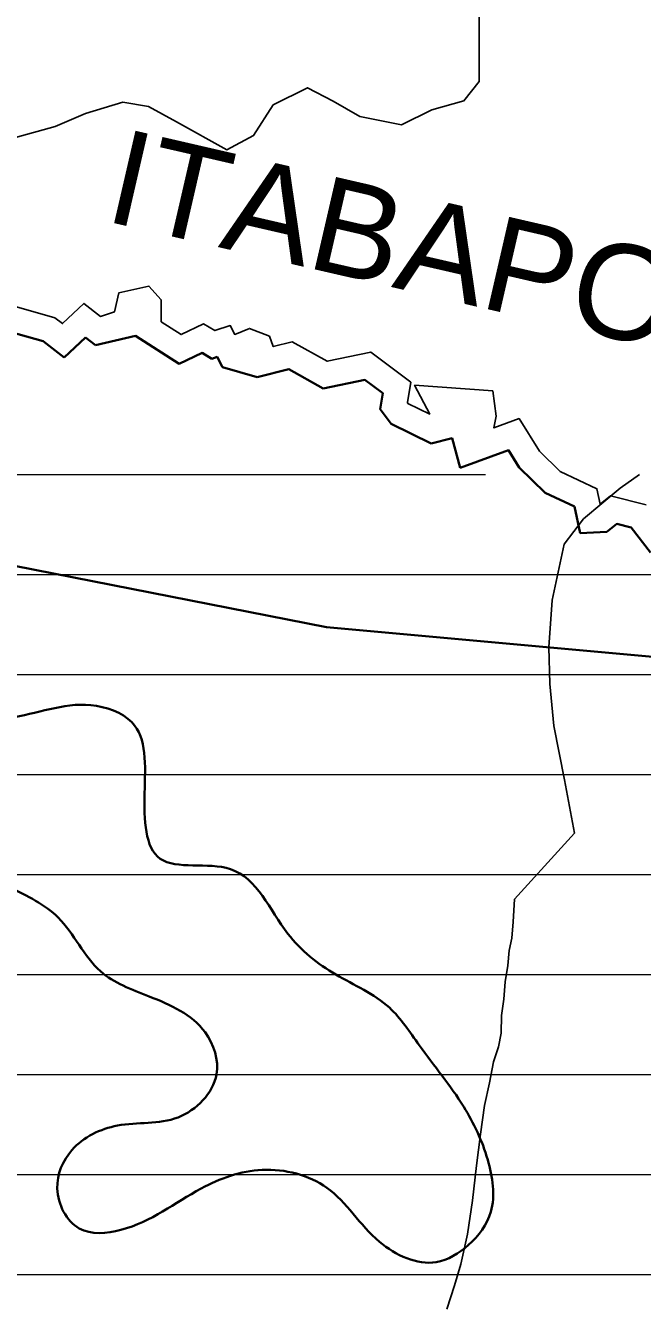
# Model space of a CAD drawing. Extents: x -10.5 to 30.8, y 18.4 to 58.7.
# Drawn here: x 10.83 to 12.063, y 50.987 to 53.552 of the extents above; entities that cross this region are included whole.
import ezdxf

# ---------------------------------------------------------------- set-up
doc = ezdxf.new("R2010")
doc.units = 0
doc.header["$LTSCALE"] = 0.08
doc.linetypes.add('DASH_DOUBLE_DOT', pattern=[9.2, 5, -1.2, 0.3, -1.2, 0.3, -1.2])
for name, color, linetype, lineweight in [('12', 7, 'Continuous', 25), ('20', 7, 'DASH_DOUBLE_DOT', 35), ('29', 7, 'Continuous', 13), ('43', 7, 'Continuous', 13), ('47', 7, 'Continuous', 25), ('48', 7, 'Continuous', 35), ('9', 7, 'Continuous', 25)]:
    doc.layers.add(name, color=color, linetype=linetype, lineweight=lineweight)

msp = doc.modelspace()

# ---------------------------------------------------------------- linework, layer by layer
at = {"layer": '12'}
msp.add_lwpolyline([(10.81009, 53.32855), (10.88946, 53.35065), (10.94956, 53.37692), (11.02464, 53.39903), (11.07605, 53.39064), (11.13166, 53.35978), (11.2322, 53.30424), (11.28587, 53.33257), (11.32466, 53.39363), (11.39336, 53.42802), (11.4447, 53.40126), (11.49817, 53.37041), (11.58169, 53.35371), (11.64181, 53.38406), (11.70616, 53.40214), (11.7363, 53.44079), (11.73648, 53.49181), (11.73684, 53.59589)], dxfattribs=at)
at = {"layer": '20'}
msp.add_lwpolyline([(10.79886, 52.94002), (10.86532, 52.92121), (10.90749, 52.88884), (10.94985, 52.92896), (10.96981, 52.91336), (11.0497, 52.93231), (11.13687, 52.8758), (11.183, 52.8977), (11.20219, 52.88615), (11.21328, 52.88976), (11.22374, 52.86923), (11.29305, 52.84918), (11.35593, 52.86524), (11.42457, 52.82671), (11.50783, 52.84434), (11.54416, 52.81703), (11.53858, 52.78532), (11.56057, 52.7561), (11.64038, 52.71687), (11.6825, 52.72762), (11.69896, 52.66809), (11.79498, 52.70359), (11.81682, 52.66889), (11.86855, 52.618), (11.92715, 52.59057), (11.93861, 52.53739), (11.99156, 52.54006), (12.0115, 52.55589), (12.0406, 52.54866), (12.07895, 52.49862)], dxfattribs=at)
at = {"layer": '29', "linetype": 'DASH_DOUBLE_DOT', "lineweight": 35}
msp.add_lwpolyline([(10.79886, 52.94002), (10.86532, 52.92121), (10.90749, 52.88884), (10.94985, 52.92896), (10.96981, 52.91336), (11.0497, 52.93231), (11.13687, 52.8758), (11.183, 52.8977), (11.20219, 52.88615), (11.21328, 52.88976), (11.22374, 52.86923), (11.29305, 52.84918), (11.35593, 52.86524), (11.42457, 52.82671), (11.50783, 52.84434), (11.54416, 52.81703), (11.53858, 52.78532), (11.56057, 52.7561), (11.64038, 52.71687), (11.6825, 52.72762), (11.69896, 52.66809), (11.79498, 52.70359), (11.81682, 52.66889), (11.86855, 52.618), (11.92715, 52.59057), (11.93861, 52.53739), (11.99156, 52.54006), (12.0115, 52.55589), (12.0406, 52.54866), (12.07895, 52.49862)], dxfattribs=at)
at = {"layer": '43'}
for p, q in [((4.719, 52.6548), (11.74932, 52.6548)), ((4.719, 52.4548), (12.30135, 52.4548)), ((4.719, 52.2548), (12.92186, 52.2548)), ((4.719, 52.0548), (14.29713, 52.0548)), ((4.719, 51.8548), (15.2159, 51.8548)), ((4.719, 51.6548), (15.4387, 51.6548)), ((4.719, 51.4548), (15.65105, 51.4548)), ((4.719, 51.2548), (15.6669, 51.2548)), ((4.719, 51.0548), (15.6026, 51.0548))]:
    msp.add_line(p, q, dxfattribs=at)
msp.add_lwpolyline([(12.07895, 52.49862), (12.0406, 52.54866), (12.0115, 52.55589), (11.99156, 52.54006), (11.93861, 52.53739), (11.92715, 52.59057), (11.86855, 52.618), (11.81682, 52.66889), (11.79498, 52.70359), (11.69896, 52.66809), (11.6825, 52.72762), (11.64038, 52.71687), (11.56057, 52.7561), (11.53858, 52.78532), (11.54416, 52.81703), (11.50783, 52.84434), (11.42457, 52.82671), (11.35593, 52.86524), (11.29305, 52.84918), (11.22374, 52.86923), (11.21328, 52.88976), (11.20219, 52.88615), (11.183, 52.8977), (11.13687, 52.8758), (11.0497, 52.93231), (10.96981, 52.91336), (10.94985, 52.92896), (10.90749, 52.88884), (10.86532, 52.92121), (10.79886, 52.94002)], dxfattribs=at)
msp.add_lwpolyline([(12.07895, 52.49862), (12.0406, 52.54866), (12.0115, 52.55589), (11.99156, 52.54006), (11.93861, 52.53739), (11.92715, 52.59057), (11.86855, 52.618), (11.81682, 52.66889), (11.79498, 52.70359), (11.69896, 52.66809), (11.6825, 52.72762), (11.64038, 52.71687), (11.56057, 52.7561), (11.53858, 52.78532), (11.54416, 52.81703), (11.50783, 52.84434), (11.42457, 52.82671), (11.35593, 52.86524), (11.29305, 52.84918), (11.22374, 52.86923), (11.21328, 52.88976), (11.20219, 52.88615), (11.183, 52.8977), (11.13687, 52.8758), (11.0497, 52.93231), (10.96981, 52.91336), (10.94985, 52.92896), (10.90749, 52.88884), (10.86532, 52.92121), (10.79886, 52.94002)], dxfattribs=at)
at = {"layer": '47'}
msp.add_lwpolyline([(10.80273, 52.99244), (10.88884, 52.96807), (10.90399, 52.95645), (10.94663, 52.99684), (10.97985, 52.97087), (11.00779, 52.98006), (11.01613, 53.01787), (11.07656, 53.03135), (11.1012, 53.00392), (11.1012, 52.96029), (11.14076, 52.93465), (11.18587, 52.95608), (11.20861, 52.94239), (11.2392, 52.95234), (11.24811, 52.93484), (11.27746, 52.94684), (11.31756, 52.93115), (11.32521, 52.91054), (11.36316, 52.92023), (11.43287, 52.8811), (11.52006, 52.89957), (11.60035, 52.83921), (11.59317, 52.79842), (11.59432, 52.79689), (11.6379, 52.77547), (11.60756, 52.83308), (11.7639, 52.82173), (11.77068, 52.77153), (11.76625, 52.74787), (11.81631, 52.76638), (11.85721, 52.70139), (11.89837, 52.6609), (11.97211, 52.62638), (11.97874, 52.59563), (11.99933, 52.61197), (12.07051, 52.59429)], dxfattribs=at)
at = {"layer": '48'}
msp.add_lwpolyline([(13.1676, 52.19155), (11.43157, 52.34934), (10.2618, 52.57907), (10.23722, 52.58384)], dxfattribs=at)
for points in [[(9.65288, 51.32868), (9.76997, 51.37657), (9.84527, 51.42597), (9.95322, 51.50546), (10.08447, 51.64143), (10.20418, 51.75175), (10.30232, 51.72218), (10.43551, 51.77992), (10.48123, 51.87206), (10.59199, 51.89414), (10.66489, 51.88631), (10.79849, 51.82941), (10.89531, 51.76862), (10.97971, 51.66139), (11.07697, 51.61101), (11.18902, 51.53925), (11.21163, 51.45508), (11.1348, 51.36926), (11.0138, 51.35276), (10.92283, 51.30393), (10.89344, 51.22683), (10.93716, 51.14711), (11.02072, 51.14411), (11.18111, 51.22692), (11.30298, 51.26423), (11.43223, 51.22833), (11.53753, 51.12035), (11.65089, 51.07981), (11.7151, 51.11397), (11.75972, 51.1801), (11.75365, 51.28452), (11.7058, 51.39045), (11.61683, 51.51347), (11.55723, 51.58856), (11.45018, 51.65492), (11.35423, 51.73652), (11.23937, 51.86569), (11.09902, 51.88636), (11.06793, 52.01773), (11.0425, 52.15932), (10.96026, 52.19353), (10.79705, 52.16813), (10.65691, 52.194), (10.57097, 52.26482), (10.44651, 52.29012), (10.28177, 52.22831), (10.17294, 52.12801), (10.09523, 52.02138), (10.02265, 51.93555)], [(10.02265, 51.93555), (10.09523, 52.02138), (10.17294, 52.12801), (10.28177, 52.22831), (10.44651, 52.29012), (10.57097, 52.26482), (10.65691, 52.194), (10.79705, 52.16813), (10.96026, 52.19353), (11.0425, 52.15932), (11.06793, 52.01773), (11.09902, 51.88636), (11.23937, 51.86569), (11.35423, 51.73652), (11.45018, 51.65492), (11.55723, 51.58856), (11.61683, 51.51347), (11.7058, 51.39045), (11.75365, 51.28452), (11.75972, 51.1801), (11.7151, 51.11397), (11.65089, 51.07981), (11.53753, 51.12035), (11.43223, 51.22833), (11.30298, 51.26423), (11.18111, 51.22692), (11.02072, 51.14411), (10.93716, 51.14711), (10.89344, 51.22683), (10.92283, 51.30393), (11.0138, 51.35276), (11.1348, 51.36926), (11.21163, 51.45508), (11.18902, 51.53925), (11.07697, 51.61101), (10.97971, 51.66139), (10.89531, 51.76862), (10.79849, 51.82941), (10.66489, 51.88631), (10.59199, 51.89414), (10.48123, 51.87206), (10.43551, 51.77992), (10.30232, 51.72218), (10.20418, 51.75175), (10.08447, 51.64143), (9.95322, 51.50546), (9.84527, 51.42597), (9.76997, 51.37657), (9.65288, 51.32868)], [(9.65288, 51.32868), (9.76997, 51.37657), (9.84527, 51.42597), (9.95322, 51.50546), (10.08447, 51.64143), (10.20418, 51.75175), (10.30232, 51.72218), (10.43551, 51.77992), (10.48123, 51.87206), (10.59199, 51.89414), (10.66489, 51.88631), (10.79849, 51.82941), (10.89531, 51.76862), (10.97971, 51.66139), (11.07697, 51.61101), (11.18902, 51.53925), (11.21163, 51.45508), (11.1348, 51.36926), (11.0138, 51.35276), (10.92283, 51.30393), (10.89344, 51.22683), (10.93716, 51.14711), (11.02072, 51.14411), (11.18111, 51.22692), (11.30298, 51.26423), (11.43223, 51.22833), (11.53753, 51.12035), (11.65089, 51.07981), (11.7151, 51.11397), (11.75972, 51.1801), (11.75365, 51.28452), (11.7058, 51.39045), (11.61683, 51.51347), (11.55723, 51.58856), (11.45018, 51.65492), (11.35423, 51.73652), (11.23937, 51.86569), (11.09902, 51.88636), (11.06793, 52.01773), (11.0425, 52.15932), (10.96026, 52.19353), (10.79705, 52.16813), (10.65691, 52.194), (10.57097, 52.26482), (10.44651, 52.29012), (10.28177, 52.22831), (10.17294, 52.12801), (10.09523, 52.02138), (10.02265, 51.93555)], [(10.67227, 49.07775), (10.72643, 48.99765), (10.78516, 48.90176), (10.8317, 48.76462), (10.9024, 48.70477), (10.96051, 48.71832), (11.01339, 48.73205), (11.06999, 48.83422), (11.11703, 48.95758), (11.17669, 49.13258), (11.26616, 49.27005), (11.3419, 49.32985), (11.45486, 49.40395), (11.55975, 49.4106), (11.63721, 49.38698), (11.73969, 49.33641), (11.74013, 49.34682), (11.83961, 49.4735), (11.89862, 49.6329), (11.98612, 49.72354), (12.07709, 49.77238), (12.1746, 49.85224), (12.17678, 49.90426), (12.22275, 50.12665), (12.25215, 50.20375), (12.2837, 50.20783), (12.38424, 50.23548), (12.52112, 50.25662), (12.64168, 50.26271), (12.78838, 50.39291), (12.90894, 50.399), (13.04779, 50.46696), (13.13269, 50.62022), (13.21171, 50.75806), (13.39234, 50.82451), (13.44025, 50.96868), (13.46858, 51.14481), (13.53932, 51.21), (13.68142, 51.23095), (13.76586, 51.24876), (13.77111, 51.37362), (13.71785, 51.59957), (13.62907, 51.60276), (13.50742, 51.57065), (13.38074, 51.41889), (13.30696, 51.40591), (13.25367, 51.50682), (13.23935, 51.66364)], [(13.23935, 51.66364), (13.25367, 51.50682), (13.30696, 51.40591), (13.38074, 51.41889), (13.50742, 51.57065), (13.62907, 51.60276), (13.71785, 51.59957), (13.77111, 51.37362), (13.76586, 51.24876), (13.68142, 51.23095), (13.53932, 51.21), (13.46858, 51.14481), (13.44025, 50.96868), (13.39234, 50.82451), (13.21171, 50.75806), (13.13269, 50.62022), (13.04779, 50.46696), (12.90894, 50.399), (12.78838, 50.39291), (12.64168, 50.26271), (12.52112, 50.25662), (12.38424, 50.23548), (12.2837, 50.20783), (12.25215, 50.20375), (12.22275, 50.12665), (12.17678, 49.90426), (12.1746, 49.85224), (12.07709, 49.77238), (11.98612, 49.72354), (11.89862, 49.6329), (11.83961, 49.4735), (11.74013, 49.34682), (11.73969, 49.33641), (11.71814, 49.33856)]]:
    msp.add_spline(points, degree=3, dxfattribs=at)
at = {"layer": '9'}
for points in [[(12.05738, 52.6548), (12.0185, 52.62727), (11.94542, 52.56636), (11.90667, 52.51551), (11.88271, 52.40337), (11.87595, 52.30952), (11.87784, 52.23604), (11.88612, 52.15233), (11.90717, 52.04407), (11.92715, 51.9374)], [(11.92715, 51.9374), (11.80747, 51.80521), (11.80469, 51.76022), (11.80198, 51.72773), (11.7968, 51.70276), (11.79411, 51.67277), (11.78889, 51.64029), (11.78617, 51.6053), (11.78094, 51.57283), (11.78073, 51.53782), (11.77554, 51.51035), (11.76532, 51.4804), (11.75754, 51.43793), (11.74723, 51.39298), (11.73935, 51.33552), (11.73144, 51.27305), (11.72347, 51.20309), (11.71302, 51.13564), (11.70011, 51.07569), (11.68732, 51.03326), (11.67198, 50.98584)]]:
    msp.add_lwpolyline(points, dxfattribs=at)

# ---------------------------------------------------------------- texts
at = {"layer": '47', "width": 1.05}
msp.add_text(' ITABAPOANA', height=0.1896, rotation=347.02, dxfattribs=at).set_placement((10.91105, 53.17947))

doc.saveas('drawing.dxf')
